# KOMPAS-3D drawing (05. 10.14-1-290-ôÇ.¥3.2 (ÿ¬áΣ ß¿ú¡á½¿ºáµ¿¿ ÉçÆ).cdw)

Views: Вид 1
Referenced files in C:\Program Files\ASCON\KOMPAS-3D V9\Libs\: ELUSTR.LFR
Referenced files in C:\totalcmd\LANGUAGE\Cnhtkrf\Libs\: ELUSTR.LFR
Referenced files in C:\Program Files\ASCON\KOMPAS-3D V8 Plus\Libs\: ELUSTR.LFR
Referenced files in \\File-server\ПС Бурун\Проект\Program Files\ASCON\KOMPAS-3D V9\Libs\: ELUSTR.LFR
Referenced files in C:\Users\РЗА_Александр\элементы\: РЗиА.lfr|контакт_автомат, РЗиА.lfr
Referenced files in C:\Program Files\ASCON\KOMPAS-3D V10\Libs\: РЗиА.lfr|катушка реле 1, РЗиА.lfr
Referenced files in \\file-server\Проектирование\Проекты\ПС Пыть-Ях\Проектная документация\РЗА\021-РЗ\ПС Комарово\ПС Запкареллес\ПРОЕКТ\4. РЗА\II этап\ПС_24\Program Files\ASCON\KOMPAS-3D V10\Libs\: РЗиА.lfr
Referenced files in int C:\Program Files\ASCON\KOMPAS-3D V9\Libs\ELUSTR.LFR|То что надо|D:\Вяч Вас\элементы\: контактное соединение 2.frw
Referenced files in То что надо|D:\Вяч Вас\элементы\: контактное соединение 2.frw
Referenced files in \\File-server\Разное\123\: Лого1.jpg
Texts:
  РЗА_Роман
  Текст на чертеже
  Размерные надписи
  Шероховатость
  Линия-выноска #1
  Линия-выноска #2
  Линия-выноска #3
  Отклонения формы и база
  Заголовок таблицы
  Ячейка таблицы
  Стрелка вида
  Обозначение изменения
  Фигурная скобка
  Номер узла
  Марка координационной оси
  VRCB
  Выносная надпись
  Обозначение узла
  Марка/позиционное обозначение с линией-выноской
  Марка/позиционное обозначение на линии
  Марка/позиционное обозначение без линии-выноски
  int C:\Program Files\ASCON\KOMPAS-3D V9\Libs\ELUSTR.LFR|01|электрич
  int C:\Program Files\ASCON\KOMPAS-3D V9\Libs\ELUSTR.LFR|01|клемма1
  int C:\Program Files\ASCON\KOMPAS-3D V9\Libs\ELUSTR.LFR|01|катушка реле 1
  int C:\Program Files\ASCON\KOMPAS-3D V9\Libs\ELUSTR.LFR|01|клемма2
  int C:\Program Files\ASCON\KOMPAS-3D V9\Libs\ELUSTR.LFR|01|Резистор_1
  int C:\Program Files\ASCON\KOMPAS-3D V9\Libs\ELUSTR.LFR|01|2-х позиц::1
  int C:\totalcmd\LANGUAGE\Cnhtkrf\Libs\ELUSTR.LFR|Элементы|Заземление(общее обозначение)
  Элементы|Заземление(общее обозначение)
  int C:\Program Files\ASCON\KOMPAS-3D V8 Plus\Libs\ELUSTR.LFR|мои|Конт 1,5
  мои|Конт 1,5
  int C:\Program Files\ASCON\KOMPAS-3D V8 Plus\Libs\ELUSTR.LFR|ВСПОМОГАТЕЛЬНЫЕ ЦЕПИ|Светодиод 1
  ВСПОМОГАТЕЛЬНЫЕ ЦЕПИ|Светодиод 1
  int C:\Program Files\ASCON\KOMPAS-3D V9\Libs\ELUSTR.LFR|Элементики|контакт_автомат
  Элементики|контакт_автомат
  контакт_автомат
  катушка реле 1
  int C:\Program Files\ASCON\KOMPAS-3D V9\Libs\ELUSTR.LFR|Для меня|клемма2
  Для меня|клемма2
  Без имени
  CONTINUOUS0
  Стили документа
  ГОСТ2.721-74
  цепи
  табл
  Подпись в квадратике
  ссылки
  Светодиод правый
  Additional DXF text style 0
  Лит-Масса-Масштаб
  Материал-Предприятие
  Normal
  Обычный
  Термин
  Список определений
  Адрес
  Цитаты
  Форматированный
  Courier New
  Z-конец формы
  Z-начало формы
  Title Specification
  Body Specification ( left align )
  Body Specificaton ( centered )
  Body Text
  Тексты. 3,2
  ЗОНА_привяз
  heading 1
  Знак Знак Знак Знак Знак Знак
  Verdana
  Body Text 3
  Title
  текст переноса
  ТекстШаг1
  Маркировка
  клеммы, контакты
  тексты табл
  ООббыыччнныыйй
  ТТееррммиинн
  ССппииссоокк ооппррееддееллеенниийй
  ААддрреесс
  ЦЦииттааттыы
  ФФооррммааттиирроовваанннныыйй
  Z-ккооннеецц ффооррммыы
  Z-ннааччааллоо ффооррммыы
  Simplex
  Txt
  MS Sans Serif
  heading 2
  AGOpus
  footer
  russ
  Аппараты
  подписи
  txt
  Денис
  heading 8
  heading 3
  heading 6
  heading 7
  Абзац Знак
  heading 4
  heading 5
  heading 9
  Клеммник текст
  Definition Term
  Definition List
  Address
  Blockquote
  Preformatted
  z-Bottom of Form
  z-Top of Form
  Состав чартежа
  ячейка табл.
  маркировка
  rustxt
  Table Contents
  Table Heading
  Tahoma
  Ссылки
  Пояснения
  Вопрос
  Маркировка АСУ
  Скрытый
  KL1
  KL2
  KL3
  PV1
  KV1
  UGV1
  Панель А9
  Щит собственных нужд
  SF1
  L I секц.
  L II секц.
  EYG
  SN1
  Цепи питания
  АВР шинок
  обеспеченного
  питания
  Шинки
  Блок питания
  и устройство
  контроля
  изоляции шинок
  оперативной
  блокировки
  Цепи переменного тока
  Цепи питания оперативной блокировки разъединителей
  +EH1
  Цепи сигнализации
  Переключатели
  SAB5
  SAB6
  SAB7
  SAB8
  резерв
  SAB1
  SAB2
  SAB3
  SAB4
  КРУН-35 кВ
  ОРУ-110 кВ
  Маслосборник
  KSL1.1
  KSL1.2
  +EB1.1
  -EB1.1
  +EB1.2
  -EB1.2
  +EB2.1
  -EB2.1
  +EB2.2
  -EB2.2
  +EB3.1
  -EB3.1
  +EB3.2
  -EB3.2
  КРУН-10 кВ
  Организация шинок гарантированного питания блокировки разъединителей
  KH1
  KH2
  -EH1
  Шинки сигнализации
  Неисправность цепей
  разъединителей
  В АСУ
  В ЦС
  Высокий уровень
  воды
  в маслосборнике
  Высокий уровень воды
  Общепанельная лампа
  "Блинкер не поднят"
  HL1
  лампа сигнальная желтая, СКЛ-11-5-Ж-2-220
  + EH1
  SF3
  SF2
  KH3
  Неисправность шинок
  обеспеченного питания
  питания ОБР
  Оперативные цепи
  +EС1
  SF5
  -EС1
  Выход 3
  KL4
  KL5
  KL6
  Цепи оперативного
  Неисправность
  цепей питания ОБР
  Аварийное отключение
  автоматических
  выключателей
  в панели
  автомат. выкл.
  Цепи телесигнализации
  воды в
  маслосборнике
  Аварийное
  отключение
  KL4-KL6
  Реле промежуточное реле R15-2013-23-1220-WTLD
  SF4
  РАС
  данных УИС.ЛК
  сбора и передачи
  Устройство
  КРУН 10кВ
  Резерв
  телей ТИТ)
  преобразова-
  ввода 10кВ
  В шкаф N12
  В шкаф N11
  Питание оперативной
  ВВГнг-LS-0,66
  EA2-02
  EA2-01
  Автоматы
  Шкаф ввода питания
  оперативных шинок
  -EB
  +EB
  чатели
  Переклю-
  шинок
  изоляции
  устройство
  питания и
  Блок
  Цепи питания оперативной блокировки разъединителей 110 и 10кВ
  АВР
  Щит СН 0,4кВ 1 и 2 секция
  ФАЗА С !!!
  Примечания:
  1. Схема организации питания оперативных цепей блокировки разъединителей разработана на основе
  типового проекта 407-03-419.87 лист 9;
  2. Установку передающего датчика-реле уровня выполнить на месте монтажа, руководствуясь схемой
  10,08/73,001-01-ЭП4 (лист 12);
  3. Маркировка цепей АСУ см. 10.08/73.001-01-ЭУ.СБ.04.
  Состав чертежа
  Лист
  Состав чертежа.
  Организация питания оперативной блокировки и обеспеченного питания 220 В
  Цепи сигнализации. Перечень аппаратуры
  Устройство контроля
  изоляции оперативной
  KSL1
  КРУМ-35 кВ
  ~220 В, 50 Гц
  Шинки обеспеченного
  Блок питания ОБР
  Питание датчика РОС
  Питание РАС
  Отключение
  В-110 1Т от РЗТ
  через ЭМО1
  через ЭМО2
  В-110 2Т от РЗТ
  SG1
  Токовые цепи
  РЗТ 1Т
  РЗТ 2Т
  Цепи оперативного тока
  SF10
  SF9
  SF8
  SF7
  SF6
  CONTINUOUS_RGB_0_0_0_THICK_0.18
  POLYLINE_STYLE_0.18_RGB_0_0_0
  POLYLINE_STYLE_0.48_RGB_0_0_0
  CONTINUOUS_RGB_40_168_0_THICK_0.18
  POLYLINE_STYLE_0.32_RGB_0_0_0
  POLYLINE_STYLE_0.22_RGB_0_0_0
  Контакт
  Н.контр
  Шкаф сигнализации РЗТ.
  Схема электрическая принципиальная.
  Разраб.
  Галкин
  Лобачёв
  Организация шинок обеспеченного
  питания. Питание цепей ОБР.
  Схема электрическая принципиальная
  Борисов
  Реконструкция ПС 110 кВ Опорная
  (замена трансформаторов 16МВА на 40МВА)
Dimensions and other numbers on the sheet: 10/14-1-290-УА.Э3.2; 7; 01|электрич; 01|клемма1; 01|катушка реле 1; 01|клемма2; 01|Резистор_1; 01|2-х позиц::1; 6; 3,2 (надписи); 2,5 (контакты, клеммы); 3,2_; 2,5_01; 5_заголовок; 2,5 грязносинь; 3,2_зона не привяз; 2,3_; 2,5_3; 2.5; 3,5_01; 3,5_tabl; 1,8; 2,5; 3,2; 3,5; 3.5; 5; 3,2 элементы; 3,2 линия; 3,2 таблица; 3.2 маркировка; 2.5_Э5_надписи; 2.5_Э5_ссылки; 2.5_кабель; 3.2; 2.5 надписи; 3,2 (Зоны); 2.5 курсив; 5,0_белый_подчёркнутый; 3.2 фиол; 3.2 (текст); 2; 1; 8; 10; 9; 18; 20; 17; 1701; 12; 4; 3; 15; 14; 13; 11; 1702; 1946; 1947; 3-3851; 3-3854; 4-3854; 4-3851; 1703; 1948; 1101; 1102; 96; 95; 21; 24; 31; 34; 2с.ш.; 1с.ш.; 2с.ш.(питание; 1с.ш.(питание; 110кВ; 2x4; 1 и 2 с.ш. 10кВ; 19; 25; 44; 51; 43; 50; 23; 33; 22; 32; 26; 27; 16; 28; 29; 30; 49; 42; 48; 41; 47; 40; 46; 39; 52; 38; 53,54; 12,13; 05.10; 86/02-19-01-290-УА.Э3.2-; 11.12; 0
